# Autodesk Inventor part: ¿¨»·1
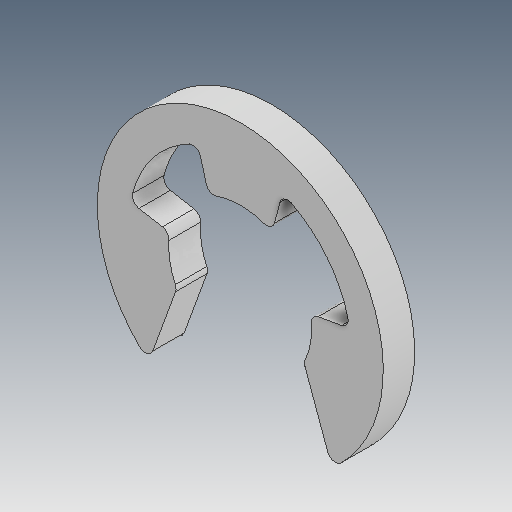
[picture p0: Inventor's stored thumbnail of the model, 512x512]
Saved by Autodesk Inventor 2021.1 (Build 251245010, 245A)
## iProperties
Created: 2013-04
Part Number: ¿¨»·1
Material: Ogólny
Document SubType Name: Modeling
Designer: user
Density: 1 g/cm^3
Appearance: Domyślna
Author: user
Revision Number: ÈÎºÎ
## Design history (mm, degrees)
feature "Í¹Ì¨-À­Éì1"
node "Bryła1"
